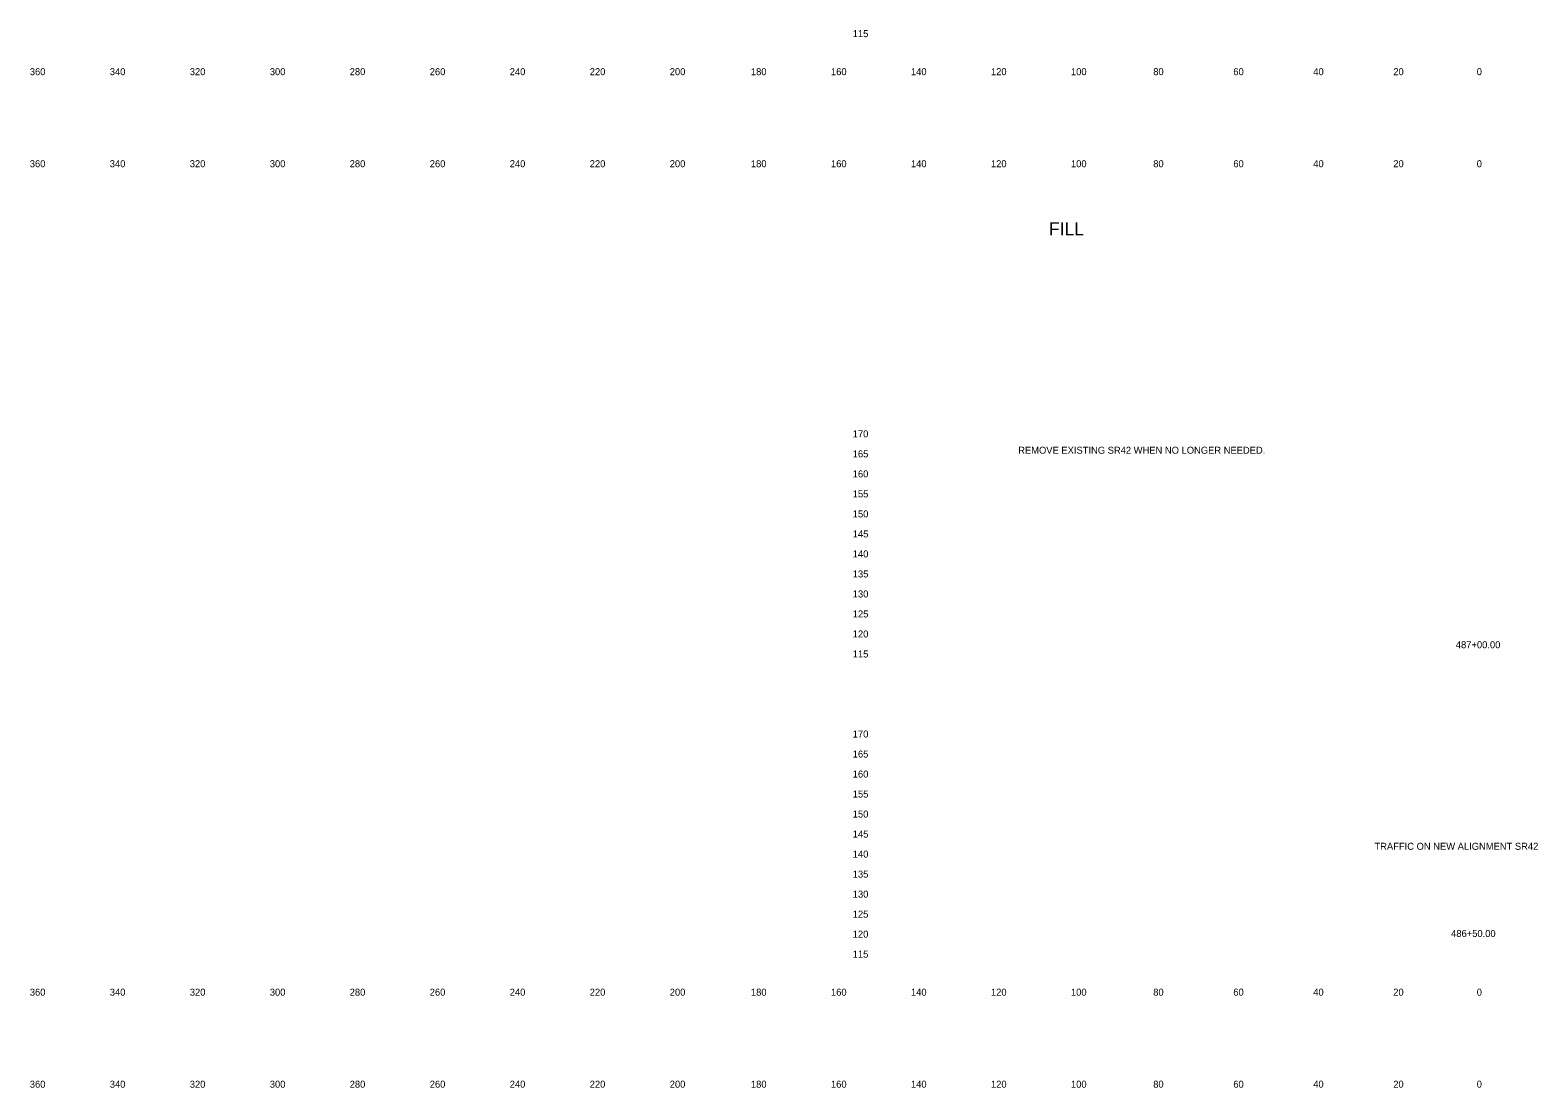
# Model space of a CAD drawing. Extents: x 21281 to 22024, y 6472 to 15208.
# Drawn here: x 21280.5 to 21657.4, y 13582.3 to 13846.6 of the extents above; entities that cross this region are included whole.
import ezdxf

# ---------------------------------------------------------------- set-up
doc = ezdxf.new("R2010")
doc.units = 0
for name, color, linetype in [('XS_SHEET_LABELS_ELEVATION', 7, 'Continuous'), ('XS_SHEET_LABELS_OFFSET', 7, 'Continuous'), ('XS_SHEET_LABELS_STATION', 7, 'Continuous')]:
    doc.layers.add(name, color=color, linetype=linetype)

msp = doc.modelspace()

# ---------------------------------------------------------------- texts
at = {"layer": 'XS_SHEET_LABELS_ELEVATION'}
for s, p in [('  115  ', (21484.84, 13844.84)), ('  170  ', (21484.84, 13744.84)), ('  165  ', (21484.84, 13739.84)), ('  160  ', (21484.84, 13734.84)), ('  155  ', (21484.84, 13729.84)), ('  150  ', (21484.84, 13724.84)), ('  145  ', (21484.84, 13719.84)), ('  140  ', (21484.84, 13714.84)), ('  135  ', (21484.84, 13709.84)), ('  130  ', (21484.84, 13704.84)), ('  125  ', (21484.84, 13699.84)), ('  120  ', (21484.84, 13694.84)), ('  115  ', (21484.84, 13689.84)), ('  170  ', (21484.84, 13669.84)), ('  165  ', (21484.84, 13664.84)), ('  160  ', (21484.84, 13659.84)), ('  155  ', (21484.84, 13654.84)), ('  150  ', (21484.84, 13649.84)), ('  145  ', (21484.84, 13644.84)), ('  140  ', (21484.84, 13639.84)), ('  135  ', (21484.84, 13634.84)), ('  130  ', (21484.84, 13629.84)), ('  125  ', (21484.84, 13624.84)), ('  120  ', (21484.84, 13619.84)), ('  115  ', (21484.84, 13614.84))]:
    msp.add_text(s, height=1.75, dxfattribs=at).set_placement(p)
at = {"layer": 'XS_SHEET_LABELS_OFFSET'}
for s, height, p in [('  360  ', 1.75, (21279.14, 13835.34)), ('  340  ', 1.75, (21299.13, 13835.34)), ('  320  ', 1.75, (21319.13, 13835.34)), ('  300  ', 1.75, (21339.13, 13835.34)), ('  280  ', 1.75, (21359.1, 13835.34)), ('  260  ', 1.75, (21379.11, 13835.34)), ('  240  ', 1.75, (21399.1, 13835.34)), ('  220  ', 1.75, (21419.1, 13835.34)), ('  200  ', 1.75, (21439.1, 13835.34)), ('  180  ', 1.75, (21459.39, 13835.34)), ('  160  ', 1.75, (21479.4, 13835.34)), ('  140  ', 1.75, (21499.39, 13835.34)), ('  120  ', 1.75, (21519.39, 13835.34)), ('  100  ', 1.75, (21539.39, 13835.34)), ('  80  ', 1.75, (21559.95, 13835.34)), ('  60  ', 1.75, (21579.97, 13835.34)), ('  40  ', 1.75, (21599.95, 13835.34)), ('  20  ', 1.75, (21619.95, 13835.34)), ('  0  ', 1.75, (21640.81, 13835.34)), ('  0  ', 1.75, (21640.81, 13835.34)), ('  360  ', 1.75, (21279.14, 13812.34)), ('  340  ', 1.75, (21299.13, 13812.34)), ('  320  ', 1.75, (21319.13, 13812.34)), ('  300  ', 1.75, (21339.13, 13812.34)), ('  280  ', 1.75, (21359.1, 13812.34)), ('  260  ', 1.75, (21379.11, 13812.34)), ('  240  ', 1.75, (21399.1, 13812.34)), ('  220  ', 1.75, (21419.1, 13812.34)), ('  200  ', 1.75, (21439.1, 13812.34)), ('  180  ', 1.75, (21459.39, 13812.34)), ('  160  ', 1.75, (21479.4, 13812.34)), ('  140  ', 1.75, (21499.39, 13812.34)), ('  120  ', 1.75, (21519.39, 13812.34)), ('  100  ', 1.75, (21539.39, 13812.34)), ('  80  ', 1.75, (21559.95, 13812.34)), ('  60  ', 1.75, (21579.97, 13812.34)), ('  40  ', 1.75, (21599.95, 13812.34)), ('  20  ', 1.75, (21619.95, 13812.34)), ('  0  ', 1.75, (21640.81, 13812.34)), ('  0  ', 1.75, (21640.81, 13812.34)), ('FILL', 3.273, (21535.18, 13795.29)), ('  360  ', 1.75, (21279.14, 13605.34)), ('  340  ', 1.75, (21299.13, 13605.34)), ('  320  ', 1.75, (21319.13, 13605.34)), ('  300  ', 1.75, (21339.13, 13605.34)), ('  280  ', 1.75, (21359.1, 13605.34)), ('  260  ', 1.75, (21379.11, 13605.34)), ('  240  ', 1.75, (21399.1, 13605.34)), ('  220  ', 1.75, (21419.1, 13605.34)), ('  200  ', 1.75, (21439.1, 13605.34)), ('  180  ', 1.75, (21459.39, 13605.34)), ('  160  ', 1.75, (21479.4, 13605.34)), ('  140  ', 1.75, (21499.39, 13605.34)), ('  120  ', 1.75, (21519.39, 13605.34)), ('  100  ', 1.75, (21539.39, 13605.34)), ('  80  ', 1.75, (21559.95, 13605.34)), ('  60  ', 1.75, (21579.97, 13605.34)), ('  40  ', 1.75, (21599.95, 13605.34)), ('  20  ', 1.75, (21619.95, 13605.34)), ('  0  ', 1.75, (21640.81, 13605.34)), ('  0  ', 1.75, (21640.81, 13605.34)), ('  360  ', 1.75, (21279.14, 13582.34)), ('  340  ', 1.75, (21299.13, 13582.34)), ('  320  ', 1.75, (21319.13, 13582.34)), ('  300  ', 1.75, (21339.13, 13582.34)), ('  280  ', 1.75, (21359.1, 13582.34)), ('  260  ', 1.75, (21379.11, 13582.34)), ('  240  ', 1.75, (21399.1, 13582.34)), ('  220  ', 1.75, (21419.1, 13582.34)), ('  200  ', 1.75, (21439.1, 13582.34)), ('  180  ', 1.75, (21459.39, 13582.34)), ('  160  ', 1.75, (21479.4, 13582.34)), ('  140  ', 1.75, (21499.39, 13582.34)), ('  120  ', 1.75, (21519.39, 13582.34)), ('  100  ', 1.75, (21539.39, 13582.34)), ('  80  ', 1.75, (21559.95, 13582.34)), ('  60  ', 1.75, (21579.97, 13582.34)), ('  40  ', 1.75, (21599.95, 13582.34)), ('  20  ', 1.75, (21619.95, 13582.34)), ('  0  ', 1.75, (21640.81, 13582.34)), ('  0  ', 1.75, (21640.81, 13582.34))]:
    msp.add_text(s, height=height, dxfattribs=at).set_placement(p)
at = {"layer": 'XS_SHEET_LABELS_STATION'}
for s, p in [('REMOVE EXISTING SR42 WHEN NO LONGER NEEDED.', (21527.5, 13740.75)), ('  487+00.00  ', (21635.59, 13692.15)), ('TRAFFIC ON NEW ALIGNMENT SR42', (21616.55, 13641.79)), ('  486+50.00  ', (21634.41, 13620))]:
    msp.add_text(s, height=1.75, dxfattribs=at).set_placement(p)

doc.saveas('drawing.dxf')
